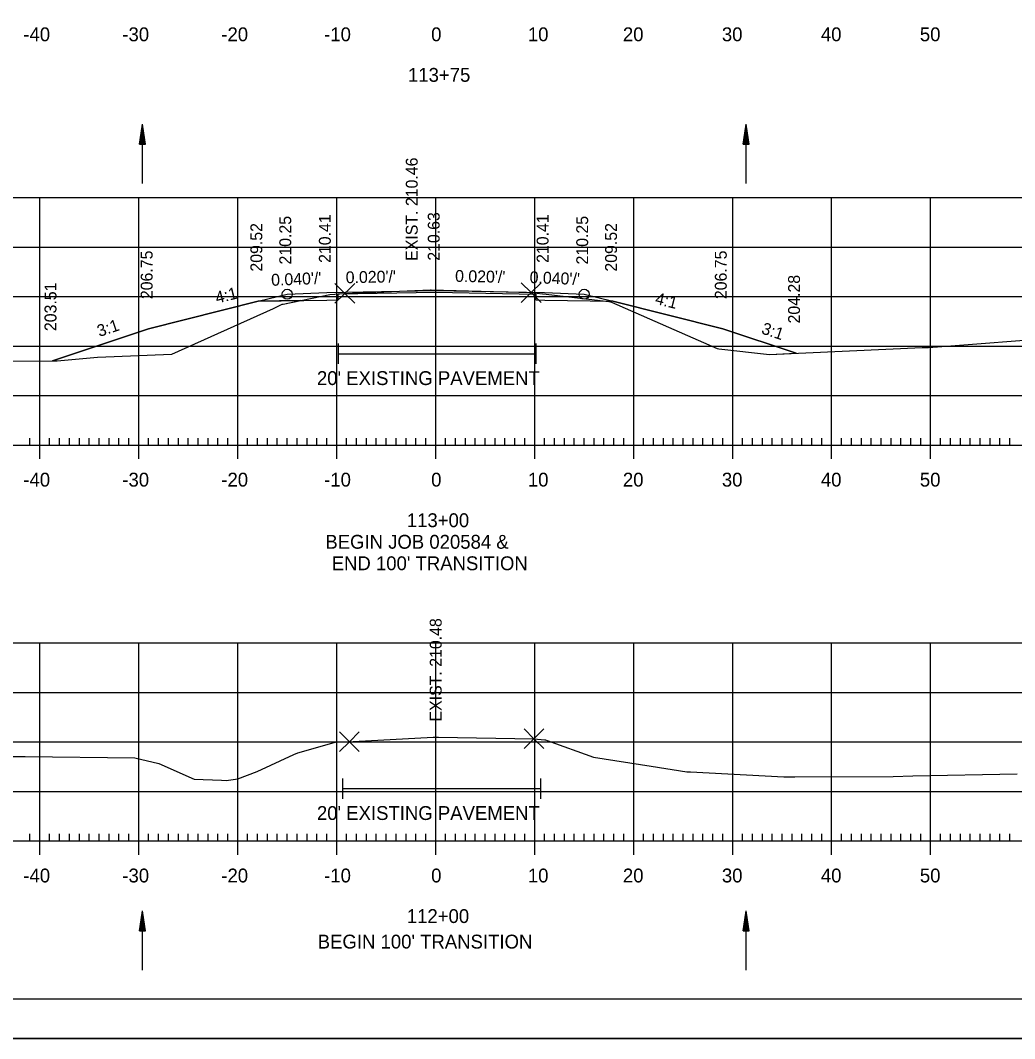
# Model space of a CAD drawing. Extents: x 1312042 to 1371461, y 379929 to 1834241.
# Drawn here: x 1371256.3 to 1371356.8, y 379928.9 to 380031.8 of the extents above; entities that cross this region are included whole.
import ezdxf

# ---------------------------------------------------------------- set-up
doc = ezdxf.new("R2010")
doc.units = 0
for name, color, linetype in [('Default', 7, 'Continuous'), ('R_Alt Surface', 7, 'Continuous'), ('R_Axis', 7, 'Continuous'), ('R_Axis Annot', 7, 'Continuous'), ('R_Border', 7, 'Continuous'), ('R_Exist Surface', 7, 'Continuous'), ('R_Fin Surface', 7, 'Continuous'), ('R_Grid', 7, 'Continuous'), ('R_No Plot', 7, 'Continuous'), ('R_Water Annot', 7, 'Continuous'), ('R_Xsect Elev', 7, 'Continuous'), ('R_Xsect Slope', 7, 'Continuous')]:
    doc.layers.add(name, color=color, linetype=linetype)

msp = doc.modelspace()

# ---------------------------------------------------------------- linework, layer by layer
at = {"layer": 'Default'}
for p, q in [((1371288.41, 379999.17), (1371288.41, 379997.11)), ((1371308.41, 379999.17), (1371308.41, 379997.11)), ((1371288.41, 379998.14), (1371308.41, 379998.14)), ((1371288.87, 379955.22), (1371288.87, 379953.16)), ((1371308.87, 379955.22), (1371308.87, 379953.16)), ((1371288.87, 379954.19), (1371308.87, 379954.19))]:
    msp.add_line(p, q, dxfattribs=at)
at = {"layer": 'R_Alt Surface'}
msp.add_lwpolyline([(1371280.36, 380003.43), (1371287.29, 380003.56), (1371288.41, 380003.59), (1371288.41, 380004.17), (1371298.28, 380004.37), (1371308.41, 380004.16), (1371308.41, 380003.58), (1371309.29, 380003.56), (1371316.19, 380003.43)], dxfattribs=at)
at = {"layer": 'R_Axis'}
for p, q in [((1371257.28, 379988.91), (1371257.28, 379989.61)), ((1371258.28, 379987.51), (1371258.28, 379990.31)), ((1371259.28, 379988.91), (1371259.28, 379989.61)), ((1371260.28, 379988.91), (1371260.28, 379989.61)), ((1371261.28, 379988.91), (1371261.28, 379989.61)), ((1371262.28, 379988.91), (1371262.28, 379989.61)), ((1371263.28, 379988.91), (1371263.28, 379989.61)), ((1371264.28, 379988.91), (1371264.28, 379989.61)), ((1371265.28, 379988.91), (1371265.28, 379989.61)), ((1371266.28, 379988.91), (1371266.28, 379989.61)), ((1371267.28, 379988.91), (1371267.28, 379989.61)), ((1371268.28, 379987.51), (1371268.28, 379990.31)), ((1371269.28, 379988.91), (1371269.28, 379989.61)), ((1371270.28, 379988.91), (1371270.28, 379989.61)), ((1371271.28, 379988.91), (1371271.28, 379989.61)), ((1371272.28, 379988.91), (1371272.28, 379989.61)), ((1371273.28, 379988.91), (1371273.28, 379989.61)), ((1371274.28, 379988.91), (1371274.28, 379989.61)), ((1371275.28, 379988.91), (1371275.28, 379989.61)), ((1371276.28, 379988.91), (1371276.28, 379989.61)), ((1371277.28, 379988.91), (1371277.28, 379989.61)), ((1371278.28, 379987.51), (1371278.28, 379990.31)), ((1371279.28, 379988.91), (1371279.28, 379989.61)), ((1371280.28, 379988.91), (1371280.28, 379989.61)), ((1371281.28, 379988.91), (1371281.28, 379989.61)), ((1371282.28, 379988.91), (1371282.28, 379989.61)), ((1371283.28, 379988.91), (1371283.28, 379989.61)), ((1371284.28, 379988.91), (1371284.28, 379989.61)), ((1371285.28, 379988.91), (1371285.28, 379989.61)), ((1371286.28, 379988.91), (1371286.28, 379989.61)), ((1371287.28, 379988.91), (1371287.28, 379989.61)), ((1371288.28, 379987.51), (1371288.28, 379990.31)), ((1371289.28, 379988.91), (1371289.28, 379989.61)), ((1371290.28, 379988.91), (1371290.28, 379989.61)), ((1371291.28, 379988.91), (1371291.28, 379989.61)), ((1371292.28, 379988.91), (1371292.28, 379989.61)), ((1371293.28, 379988.91), (1371293.28, 379989.61)), ((1371294.28, 379988.91), (1371294.28, 379989.61)), ((1371295.28, 379988.91), (1371295.28, 379989.61)), ((1371296.28, 379988.91), (1371296.28, 379989.61)), ((1371297.28, 379988.91), (1371297.28, 379989.61)), ((1371298.28, 379987.51), (1371298.28, 379990.31)), ((1371299.28, 379988.91), (1371299.28, 379989.61)), ((1371300.28, 379988.91), (1371300.28, 379989.61)), ((1371301.28, 379988.91), (1371301.28, 379989.61)), ((1371302.28, 379988.91), (1371302.28, 379989.61)), ((1371303.28, 379988.91), (1371303.28, 379989.61)), ((1371304.28, 379988.91), (1371304.28, 379989.61)), ((1371305.28, 379988.91), (1371305.28, 379989.61)), ((1371306.28, 379988.91), (1371306.28, 379989.61)), ((1371307.28, 379988.91), (1371307.28, 379989.61)), ((1371308.28, 379987.51), (1371308.28, 379990.31)), ((1371309.28, 379988.91), (1371309.28, 379989.61)), ((1371310.28, 379988.91), (1371310.28, 379989.61)), ((1371311.28, 379988.91), (1371311.28, 379989.61)), ((1371312.28, 379988.91), (1371312.28, 379989.61)), ((1371313.28, 379988.91), (1371313.28, 379989.61)), ((1371314.28, 379988.91), (1371314.28, 379989.61)), ((1371315.28, 379988.91), (1371315.28, 379989.61)), ((1371316.28, 379988.91), (1371316.28, 379989.61)), ((1371317.28, 379988.91), (1371317.28, 379989.61)), ((1371318.28, 379987.51), (1371318.28, 379990.31)), ((1371319.28, 379988.91), (1371319.28, 379989.61)), ((1371320.28, 379988.91), (1371320.28, 379989.61)), ((1371321.28, 379988.91), (1371321.28, 379989.61)), ((1371322.28, 379988.91), (1371322.28, 379989.61)), ((1371323.28, 379988.91), (1371323.28, 379989.61)), ((1371324.28, 379988.91), (1371324.28, 379989.61)), ((1371325.28, 379988.91), (1371325.28, 379989.61)), ((1371326.28, 379988.91), (1371326.28, 379989.61)), ((1371327.28, 379988.91), (1371327.28, 379989.61)), ((1371328.28, 379987.51), (1371328.28, 379990.31)), ((1371329.28, 379988.91), (1371329.28, 379989.61)), ((1371330.28, 379988.91), (1371330.28, 379989.61)), ((1371331.28, 379988.91), (1371331.28, 379989.61)), ((1371332.28, 379988.91), (1371332.28, 379989.61)), ((1371333.28, 379988.91), (1371333.28, 379989.61)), ((1371334.28, 379988.91), (1371334.28, 379989.61)), ((1371335.28, 379988.91), (1371335.28, 379989.61)), ((1371336.28, 379988.91), (1371336.28, 379989.61)), ((1371337.28, 379988.91), (1371337.28, 379989.61)), ((1371338.28, 379987.51), (1371338.28, 379990.31)), ((1371339.28, 379988.91), (1371339.28, 379989.61)), ((1371340.28, 379988.91), (1371340.28, 379989.61)), ((1371341.28, 379988.91), (1371341.28, 379989.61)), ((1371342.28, 379988.91), (1371342.28, 379989.61)), ((1371343.28, 379988.91), (1371343.28, 379989.61)), ((1371344.28, 379988.91), (1371344.28, 379989.61)), ((1371345.28, 379988.91), (1371345.28, 379989.61)), ((1371346.28, 379988.91), (1371346.28, 379989.61)), ((1371347.28, 379988.91), (1371347.28, 379989.61)), ((1371348.28, 379987.51), (1371348.28, 379990.31)), ((1371349.28, 379988.91), (1371349.28, 379989.61)), ((1371350.28, 379988.91), (1371350.28, 379989.61)), ((1371351.28, 379988.91), (1371351.28, 379989.61)), ((1371352.28, 379988.91), (1371352.28, 379989.61)), ((1371353.28, 379988.91), (1371353.28, 379989.61)), ((1371354.28, 379988.91), (1371354.28, 379989.61)), ((1371355.28, 379988.91), (1371355.28, 379989.61)), ((1371356.28, 379988.91), (1371356.28, 379989.61)), ((1371158.28, 379988.91), (1371438.28, 379988.91)), ((1371258.28, 379947.51), (1371258.28, 379950.31)), ((1371268.28, 379947.51), (1371268.28, 379950.31)), ((1371278.28, 379947.51), (1371278.28, 379950.31)), ((1371288.28, 379947.51), (1371288.28, 379950.31)), ((1371298.28, 379947.51), (1371298.28, 379950.31)), ((1371308.28, 379947.51), (1371308.28, 379950.31)), ((1371318.28, 379947.51), (1371318.28, 379950.31)), ((1371328.28, 379947.51), (1371328.28, 379950.31)), ((1371338.28, 379947.51), (1371338.28, 379950.31)), ((1371348.28, 379947.51), (1371348.28, 379950.31)), ((1371257.28, 379948.91), (1371257.28, 379949.61)), ((1371259.28, 379948.91), (1371259.28, 379949.61)), ((1371260.28, 379948.91), (1371260.28, 379949.61)), ((1371261.28, 379948.91), (1371261.28, 379949.61)), ((1371262.28, 379948.91), (1371262.28, 379949.61)), ((1371263.28, 379948.91), (1371263.28, 379949.61)), ((1371264.28, 379948.91), (1371264.28, 379949.61)), ((1371265.28, 379948.91), (1371265.28, 379949.61)), ((1371266.28, 379948.91), (1371266.28, 379949.61)), ((1371267.28, 379948.91), (1371267.28, 379949.61)), ((1371269.28, 379948.91), (1371269.28, 379949.61)), ((1371270.28, 379948.91), (1371270.28, 379949.61)), ((1371271.28, 379948.91), (1371271.28, 379949.61)), ((1371272.28, 379948.91), (1371272.28, 379949.61)), ((1371273.28, 379948.91), (1371273.28, 379949.61)), ((1371274.28, 379948.91), (1371274.28, 379949.61)), ((1371275.28, 379948.91), (1371275.28, 379949.61)), ((1371276.28, 379948.91), (1371276.28, 379949.61)), ((1371277.28, 379948.91), (1371277.28, 379949.61)), ((1371279.28, 379948.91), (1371279.28, 379949.61)), ((1371280.28, 379948.91), (1371280.28, 379949.61)), ((1371281.28, 379948.91), (1371281.28, 379949.61)), ((1371282.28, 379948.91), (1371282.28, 379949.61)), ((1371283.28, 379948.91), (1371283.28, 379949.61)), ((1371284.28, 379948.91), (1371284.28, 379949.61)), ((1371285.28, 379948.91), (1371285.28, 379949.61)), ((1371286.28, 379948.91), (1371286.28, 379949.61)), ((1371287.28, 379948.91), (1371287.28, 379949.61)), ((1371289.28, 379948.91), (1371289.28, 379949.61)), ((1371290.28, 379948.91), (1371290.28, 379949.61)), ((1371291.28, 379948.91), (1371291.28, 379949.61)), ((1371292.28, 379948.91), (1371292.28, 379949.61)), ((1371293.28, 379948.91), (1371293.28, 379949.61)), ((1371294.28, 379948.91), (1371294.28, 379949.61)), ((1371295.28, 379948.91), (1371295.28, 379949.61)), ((1371296.28, 379948.91), (1371296.28, 379949.61)), ((1371297.28, 379948.91), (1371297.28, 379949.61)), ((1371299.28, 379948.91), (1371299.28, 379949.61)), ((1371300.28, 379948.91), (1371300.28, 379949.61)), ((1371301.28, 379948.91), (1371301.28, 379949.61)), ((1371302.28, 379948.91), (1371302.28, 379949.61)), ((1371303.28, 379948.91), (1371303.28, 379949.61)), ((1371304.28, 379948.91), (1371304.28, 379949.61)), ((1371305.28, 379948.91), (1371305.28, 379949.61)), ((1371306.28, 379948.91), (1371306.28, 379949.61)), ((1371307.28, 379948.91), (1371307.28, 379949.61)), ((1371309.28, 379948.91), (1371309.28, 379949.61)), ((1371310.28, 379948.91), (1371310.28, 379949.61)), ((1371311.28, 379948.91), (1371311.28, 379949.61)), ((1371312.28, 379948.91), (1371312.28, 379949.61)), ((1371313.28, 379948.91), (1371313.28, 379949.61)), ((1371314.28, 379948.91), (1371314.28, 379949.61)), ((1371315.28, 379948.91), (1371315.28, 379949.61)), ((1371316.28, 379948.91), (1371316.28, 379949.61)), ((1371317.28, 379948.91), (1371317.28, 379949.61)), ((1371319.28, 379948.91), (1371319.28, 379949.61)), ((1371320.28, 379948.91), (1371320.28, 379949.61)), ((1371321.28, 379948.91), (1371321.28, 379949.61)), ((1371322.28, 379948.91), (1371322.28, 379949.61)), ((1371323.28, 379948.91), (1371323.28, 379949.61)), ((1371324.28, 379948.91), (1371324.28, 379949.61)), ((1371325.28, 379948.91), (1371325.28, 379949.61)), ((1371326.28, 379948.91), (1371326.28, 379949.61)), ((1371327.28, 379948.91), (1371327.28, 379949.61)), ((1371329.28, 379948.91), (1371329.28, 379949.61)), ((1371330.28, 379948.91), (1371330.28, 379949.61)), ((1371331.28, 379948.91), (1371331.28, 379949.61)), ((1371332.28, 379948.91), (1371332.28, 379949.61)), ((1371333.28, 379948.91), (1371333.28, 379949.61)), ((1371334.28, 379948.91), (1371334.28, 379949.61)), ((1371335.28, 379948.91), (1371335.28, 379949.61)), ((1371336.28, 379948.91), (1371336.28, 379949.61)), ((1371337.28, 379948.91), (1371337.28, 379949.61)), ((1371339.28, 379948.91), (1371339.28, 379949.61)), ((1371340.28, 379948.91), (1371340.28, 379949.61)), ((1371341.28, 379948.91), (1371341.28, 379949.61)), ((1371342.28, 379948.91), (1371342.28, 379949.61)), ((1371343.28, 379948.91), (1371343.28, 379949.61)), ((1371344.28, 379948.91), (1371344.28, 379949.61)), ((1371345.28, 379948.91), (1371345.28, 379949.61)), ((1371346.28, 379948.91), (1371346.28, 379949.61)), ((1371347.28, 379948.91), (1371347.28, 379949.61)), ((1371349.28, 379948.91), (1371349.28, 379949.61)), ((1371350.28, 379948.91), (1371350.28, 379949.61)), ((1371351.28, 379948.91), (1371351.28, 379949.61)), ((1371352.28, 379948.91), (1371352.28, 379949.61)), ((1371353.28, 379948.91), (1371353.28, 379949.61)), ((1371354.28, 379948.91), (1371354.28, 379949.61)), ((1371355.28, 379948.91), (1371355.28, 379949.61)), ((1371356.28, 379948.91), (1371356.28, 379949.61)), ((1371158.28, 379948.91), (1371438.28, 379948.91))]:
    msp.add_line(p, q, dxfattribs=at)
at = {"layer": 'R_Border'}
msp.add_line((1371456.46, 379932.91), (1371140.28, 379932.91), dxfattribs=at)
at = {"layer": 'R_Exist Surface'}
for points in [[(1371250.09, 379997.37), (1371260.04, 379997.42), (1371264.12, 379997.77), (1371271.63, 379998.09), (1371281.89, 380002.72), (1371282.78, 380003.13), (1371282.86, 380003.15), (1371287.59, 380004.13), (1371289.1, 380004.23), (1371289.1, 380004.23), (1371297.75, 380004.6), (1371297.78, 380004.6), (1371297.83, 380004.6), (1371307.93, 380004.31), (1371309.06, 380004.2), (1371309.13, 380004.19), (1371315.77, 380003.42), (1371315.83, 380003.41), (1371316.03, 380003.33), (1371326.72, 379998.65), (1371326.88, 379998.63), (1371331.99, 379998.07), (1371347.44, 379998.75), (1371347.77, 379998.77), (1371348.05, 379998.78), (1371350.76, 379998.98), (1371359.47, 379999.63)], [(1371242.43, 379957.45), (1371256.8, 379957.44), (1371267.87, 379957.29), (1371270.31, 379956.74), (1371273.87, 379955.16), (1371276.63, 379955.03), (1371277.12, 379955.01), (1371278.28, 379955.19), (1371280.23, 379955.93), (1371283.95, 379957.63), (1371284.36, 379957.82), (1371288.01, 379958.85), (1371288.12, 379958.89), (1371288.16, 379958.89), (1371289.56, 379958.93), (1371289.94, 379958.95), (1371298.03, 379959.38), (1371298.55, 379959.38), (1371308.2, 379959.23), (1371309.31, 379959.13), (1371309.36, 379959.12), (1371309.55, 379959.06), (1371314.22, 379957.38), (1371320.03, 379956.46), (1371323.64, 379955.9), (1371324.03, 379955.88), (1371333.45, 379955.38), (1371334.57, 379955.38), (1371344.51, 379955.4), (1371346.49, 379955.49), (1371357.02, 379955.7)]]:
    msp.add_lwpolyline(points, dxfattribs=at)
at = {"layer": 'R_Fin Surface'}
msp.add_lwpolyline([(1371259.56, 379997.42), (1371259.57, 379997.42), (1371269.28, 380000.65), (1371280.36, 380003.43), (1371283.28, 380004.15), (1371287.28, 380004.31), (1371298.28, 380004.53), (1371309.28, 380004.31), (1371313.28, 380004.15), (1371316.19, 380003.43), (1371327.28, 380000.65), (1371334.68, 379998.19)], dxfattribs=at)
at = {"layer": 'R_Grid'}
for p, q in [((1371158.28, 380013.91), (1371438.28, 380013.91)), ((1371258.28, 379988.91), (1371258.28, 380013.91)), ((1371268.28, 379988.91), (1371268.28, 380013.91)), ((1371278.28, 379988.91), (1371278.28, 380013.91)), ((1371288.28, 379988.91), (1371288.28, 380013.91)), ((1371298.28, 379988.91), (1371298.28, 380013.91)), ((1371308.28, 379988.91), (1371308.28, 380013.91)), ((1371318.28, 379988.91), (1371318.28, 380013.91)), ((1371328.28, 379988.91), (1371328.28, 380013.91)), ((1371338.28, 379988.91), (1371338.28, 380013.91)), ((1371348.28, 379988.91), (1371348.28, 380013.91)), ((1371158.28, 380008.91), (1371438.28, 380008.91)), ((1371158.28, 380003.91), (1371438.28, 380003.91)), ((1371158.28, 379998.91), (1371438.28, 379998.91)), ((1371158.28, 379993.91), (1371438.28, 379993.91)), ((1371158.28, 379988.91), (1371438.28, 379988.91)), ((1371158.28, 379968.91), (1371438.28, 379968.91)), ((1371258.28, 379948.91), (1371258.28, 379968.91)), ((1371268.28, 379948.91), (1371268.28, 379968.91)), ((1371278.28, 379948.91), (1371278.28, 379968.91)), ((1371288.28, 379948.91), (1371288.28, 379968.91)), ((1371298.28, 379948.91), (1371298.28, 379968.91)), ((1371308.28, 379948.91), (1371308.28, 379968.91)), ((1371318.28, 379948.91), (1371318.28, 379968.91)), ((1371328.28, 379948.91), (1371328.28, 379968.91)), ((1371338.28, 379948.91), (1371338.28, 379968.91)), ((1371348.28, 379948.91), (1371348.28, 379968.91)), ((1371158.28, 379963.91), (1371438.28, 379963.91)), ((1371158.28, 379958.91), (1371438.28, 379958.91)), ((1371158.28, 379953.91), (1371438.28, 379953.91)), ((1371158.28, 379948.91), (1371438.28, 379948.91))]:
    msp.add_line(p, q, dxfattribs=at)
at = {"layer": 'R_No Plot'}
msp.add_line((1371127.88, 379928.93), (1371461.21, 379928.93), dxfattribs=at)
for points in [[(1371127.87, 380142.26), (1371461.21, 380142.26), (1371461.21, 379928.93), (1371127.87, 379928.93)], [(1371374.2, 380138.37), (1371374.2, 380128.49), (1371409.93, 380128.49), (1371409.93, 380125.57), (1371433.13, 380125.57), (1371433.13, 380101.24), (1371456.46, 380101.24), (1371456.46, 379932.91), (1371140.28, 379932.91), (1371140.28, 380138.37)], [(1371259.58, 379997.42), (1371260.04, 379997.42), (1371264.12, 379997.77), (1371271.63, 379998.09), (1371281.89, 380002.72), (1371282.78, 380003.13), (1371282.86, 380003.15), (1371284.61, 380003.51), (1371280.36, 380003.43), (1371269.28, 380000.65)], [(1371315.66, 380003.44), (1371315.77, 380003.42), (1371315.83, 380003.41), (1371316.03, 380003.33), (1371326.72, 379998.65), (1371326.88, 379998.63), (1371331.99, 379998.07), (1371334.68, 379998.19), (1371327.28, 380000.65), (1371316.19, 380003.43)]]:
    msp.add_lwpolyline(points, close=True, dxfattribs=at)
for points in [[(1371289.1, 380004.23), (1371288.1, 380005.23), (1371289.1, 380004.23), (1371288.1, 380003.23), (1371289.1, 380004.23), (1371290.1, 380003.23), (1371289.1, 380004.23), (1371290.1, 380005.23)], [(1371307.93, 380004.31), (1371306.93, 380005.31), (1371307.93, 380004.31), (1371306.93, 380003.31), (1371307.93, 380004.31), (1371308.93, 380003.31), (1371307.93, 380004.31), (1371308.93, 380005.31)], [(1371289.56, 379958.93), (1371288.56, 379959.93), (1371289.56, 379958.93), (1371288.56, 379957.93), (1371289.56, 379958.93), (1371290.56, 379957.93), (1371289.56, 379958.93), (1371290.56, 379959.93)], [(1371308.2, 379959.23), (1371307.2, 379960.23), (1371308.2, 379959.23), (1371307.2, 379958.23), (1371308.2, 379959.23), (1371309.2, 379958.23), (1371308.2, 379959.23), (1371309.2, 379960.23)]]:
    msp.add_lwpolyline(points, dxfattribs=at)
for centre in [(1371283.28, 380004.15), (1371313.28, 380004.15)]:
    msp.add_circle(centre, 0.5, dxfattribs=at)
at = {"layer": 'R_Water Annot'}
for p, q in [((1371268.37, 380019.32), (1371268.67, 380021.32)), ((1371268.67, 380015.32), (1371268.67, 380021.32)), ((1371268.97, 380019.32), (1371268.67, 380021.32)), ((1371329.35, 380019.32), (1371329.65, 380021.32)), ((1371329.65, 380015.32), (1371329.65, 380021.32)), ((1371329.95, 380019.32), (1371329.65, 380021.32)), ((1371268.42, 380019.32), (1371268.67, 380020.98)), ((1371268.48, 380019.32), (1371268.67, 380020.64)), ((1371268.53, 380019.32), (1371268.67, 380020.31)), ((1371268.92, 380019.32), (1371268.67, 380020.98)), ((1371268.87, 380019.32), (1371268.67, 380020.64)), ((1371268.82, 380019.32), (1371268.67, 380020.31)), ((1371329.4, 380019.32), (1371329.65, 380020.98)), ((1371329.45, 380019.32), (1371329.65, 380020.64)), ((1371329.5, 380019.32), (1371329.65, 380020.31)), ((1371329.9, 380019.32), (1371329.65, 380020.98)), ((1371329.85, 380019.32), (1371329.65, 380020.64)), ((1371329.8, 380019.32), (1371329.65, 380020.31)), ((1371268.37, 380019.32), (1371268.97, 380019.32)), ((1371268.58, 380019.32), (1371268.67, 380019.97)), ((1371268.63, 380019.32), (1371268.67, 380019.63)), ((1371268.77, 380019.32), (1371268.67, 380019.97)), ((1371268.72, 380019.32), (1371268.67, 380019.63)), ((1371329.35, 380019.32), (1371329.95, 380019.32)), ((1371329.55, 380019.32), (1371329.65, 380019.97)), ((1371329.6, 380019.32), (1371329.65, 380019.63)), ((1371329.75, 380019.32), (1371329.65, 380019.97)), ((1371329.7, 380019.32), (1371329.65, 380019.63)), ((1371268.37, 379939.83), (1371268.67, 379941.83)), ((1371268.42, 379939.83), (1371268.67, 379941.5)), ((1371268.48, 379939.83), (1371268.67, 379941.15)), ((1371268.67, 379935.83), (1371268.67, 379941.83)), ((1371268.97, 379939.83), (1371268.67, 379941.83)), ((1371268.92, 379939.83), (1371268.67, 379941.5)), ((1371268.87, 379939.83), (1371268.67, 379941.15)), ((1371329.35, 379939.83), (1371329.65, 379941.83)), ((1371329.4, 379939.83), (1371329.65, 379941.5)), ((1371329.45, 379939.83), (1371329.65, 379941.15)), ((1371329.65, 379935.83), (1371329.65, 379941.83)), ((1371329.95, 379939.83), (1371329.65, 379941.83)), ((1371329.9, 379939.83), (1371329.65, 379941.5)), ((1371329.85, 379939.83), (1371329.65, 379941.15)), ((1371268.53, 379939.83), (1371268.67, 379940.82)), ((1371268.58, 379939.83), (1371268.67, 379940.48)), ((1371268.63, 379939.83), (1371268.67, 379940.15)), ((1371268.82, 379939.83), (1371268.67, 379940.82)), ((1371268.77, 379939.83), (1371268.67, 379940.48)), ((1371268.72, 379939.83), (1371268.67, 379940.15)), ((1371329.5, 379939.83), (1371329.65, 379940.82)), ((1371329.55, 379939.83), (1371329.65, 379940.48)), ((1371329.6, 379939.83), (1371329.65, 379940.15)), ((1371329.8, 379939.83), (1371329.65, 379940.82)), ((1371329.75, 379939.83), (1371329.65, 379940.48)), ((1371329.7, 379939.83), (1371329.65, 379940.15)), ((1371268.37, 379939.83), (1371268.97, 379939.83)), ((1371329.35, 379939.83), (1371329.95, 379939.83))]:
    msp.add_line(p, q, dxfattribs=at)

# ---------------------------------------------------------------- texts
at = {"layer": 'R_Axis Annot'}
for s, p in [('-40', (1371256.62, 380029.71)), ('-30', (1371266.62, 380029.71)), ('-20', (1371276.62, 380029.71)), ('-10', (1371287.01, 380029.71)), ('0', (1371297.82, 380029.71)), ('10', (1371307.59, 380029.71)), ('20', (1371317.19, 380029.71)), ('30', (1371327.19, 380029.71)), ('40', (1371337.19, 380029.71)), ('50', (1371347.19, 380029.71)), ('113+75', (1371295.48, 380025.61)), ("20' EXISTING PAVEMENT", (1371286.28, 379994.97)), ('-40', (1371256.62, 379984.71)), ('-30', (1371266.62, 379984.71)), ('-20', (1371276.62, 379984.71)), ('-10', (1371287.01, 379984.71)), ('0', (1371297.82, 379984.71)), ('10', (1371307.59, 379984.71)), ('20', (1371317.19, 379984.71)), ('30', (1371327.19, 379984.71)), ('40', (1371337.19, 379984.71)), ('50', (1371347.19, 379984.71)), ('113+00', (1371295.36, 379980.61)), ('BEGIN JOB 020584 &', (1371287.13, 379978.43)), ("END 100' TRANSITION", (1371287.77, 379976.26)), ("20' EXISTING PAVEMENT", (1371286.28, 379951.02)), ('-40', (1371256.62, 379944.71)), ('-30', (1371266.62, 379944.71)), ('-20', (1371276.62, 379944.71)), ('-10', (1371287.01, 379944.71)), ('0', (1371297.82, 379944.71)), ('10', (1371307.59, 379944.71)), ('20', (1371317.19, 379944.71)), ('30', (1371327.19, 379944.71)), ('40', (1371337.19, 379944.71)), ('50', (1371347.19, 379944.71)), ('112+00', (1371295.36, 379940.61)), ("BEGIN 100' TRANSITION", (1371286.36, 379938.03))]:
    msp.add_text(s, height=1.4, dxfattribs=at).set_placement(p)
at = {"layer": 'R_Xsect Elev'}
for s, p in [('EXIST. 210.46', (1371296.46, 380007.52)), ('210.25', (1371283.68, 380007.15)), ('210.41', (1371287.68, 380007.31)), ('210.63', (1371298.68, 380007.53)), ('210.41', (1371309.68, 380007.31)), ('210.25', (1371313.68, 380007.15)), ('209.52', (1371280.76, 380006.43)), ('209.52', (1371316.59, 380006.43)), ('206.75', (1371269.68, 380003.65)), ('206.75', (1371327.68, 380003.65)), ('204.28', (1371335.08, 380001.19)), ('203.51', (1371259.96, 380000.42)), ('203.51', (1371259.97, 380000.42)), ('EXIST. 210.48', (1371298.88, 379960.97))]:
    msp.add_text(s, height=1.2, rotation=90, dxfattribs=at).set_placement(p)
at = {"layer": 'R_Xsect Slope'}
for s, rotation, p in [("0.040'/'", 2.2906, (1371281.68, 380004.99)), ("0.020'/'", 1.1458, (1371289.2, 380005.25)), ("0.020'/'", 358.8542, (1371300.23, 380005.4)), ("0.040'/'", 357.7094, (1371307.75, 380005.28)), ('4:1', 14.0362, (1371276.18, 380003.19)), ('4:1', 345.9638, (1371320.37, 380003.19)), ('3:1', 18.4349, (1371264.3, 379999.82)), ('3:1', 341.5651, (1371331.1, 380000.2))]:
    msp.add_text(s, height=1.2, rotation=rotation, dxfattribs=at).set_placement(p)

doc.saveas('drawing.dxf')
